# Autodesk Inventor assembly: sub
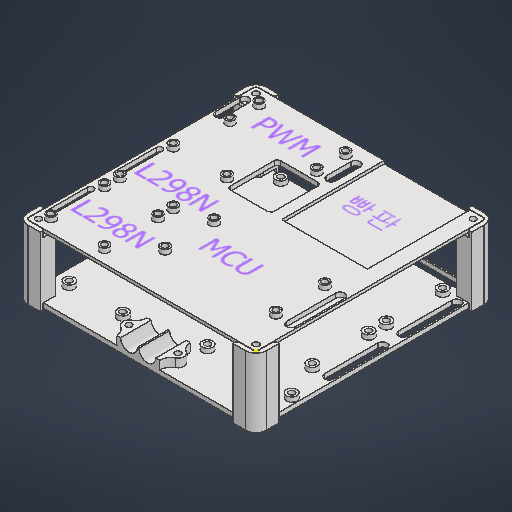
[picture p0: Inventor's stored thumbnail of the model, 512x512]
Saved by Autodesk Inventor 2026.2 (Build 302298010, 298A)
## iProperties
Created: 2026-04
Part Number: sub
Document SubType Name: Assembly
Designer: work
Author: work
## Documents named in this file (4)
- C:\Users\work\Desktop\ARD_v1\ARD_hardware\RA_Project\Substrate\sub.iam
- C:\Users\work\Desktop\ARD_v1\ARD_hardware\RA_Project\Substrate\Pillar.ipt
- C:\Users\work\Desktop\ARD_v1\ARD_hardware\RA_Project\Substrate\Power board.ipt
- C:\Users\work\Desktop\ARD_v1\ARD_hardware\RA_Project\Substrate\Control Board.ipt
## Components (6 placed, 3 different names)
1. Pillar:1 — 각도:1
2. Power board:1 — 각도:1, 각도:2, 각도:3, 각도:4
3. Control Board:1
4. Pillar:2 — 각도:3
5. Pillar:3 — 각도:4
6. Pillar:4 — 각도:2
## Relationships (4: Angle 4)
- 각도:1 [Angle]: Pillar:1 ↔ Power board:1
- 각도:2 [Angle]: Power board:1 ↔ Pillar:4
- 각도:3 [Angle]: Power board:1 ↔ Pillar:2
- 각도:4 [Angle]: Power board:1 ↔ Pillar:3
